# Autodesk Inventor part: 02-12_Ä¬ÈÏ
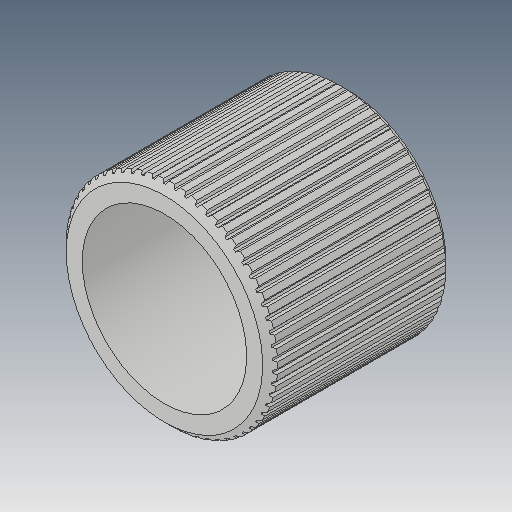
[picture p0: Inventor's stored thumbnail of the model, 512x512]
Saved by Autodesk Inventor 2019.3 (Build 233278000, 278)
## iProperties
Created: 2010-06
Part Number: 02-12_Ä¬ÈÏ
Material: Ogólny
Document SubType Name: Modeling
Designer: CADENGINEERING4
Density: 1 g/cm^3
Appearance: Domyślna
Author: CADENGINEERING4
Revision Number: ÈÎºÎ
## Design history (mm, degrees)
feature "NONE"
node "Bryła1"
